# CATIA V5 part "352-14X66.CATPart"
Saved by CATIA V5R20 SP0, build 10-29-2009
Part number: 352-14X66
Definition: NONE
Nomenclature: 352-14X66
Source: Unknown
Description: 352-14X66
Bounding box of the stored display mesh (mm): x 0 to 66, y -10 to 10, z -10 to 10
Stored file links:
  C:\Users\Utente\Desktop\IO LAVORO\3D X SITO CF\X SITO\PLASTICA\352\352-14X66.CATPart
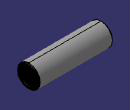
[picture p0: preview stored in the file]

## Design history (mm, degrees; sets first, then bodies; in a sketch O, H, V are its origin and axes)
Body1 "352-14X66" (main body)
  Solid1: solid without history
